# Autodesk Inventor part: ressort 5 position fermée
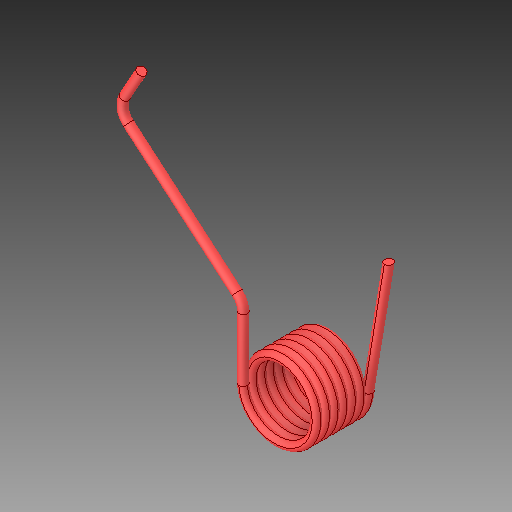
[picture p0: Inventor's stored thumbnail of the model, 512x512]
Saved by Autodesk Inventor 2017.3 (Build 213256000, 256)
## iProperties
Created: 2008-01
Part Number: ressort 5 position fermée
Material: Générique
Document SubType Name: Modeling
Designer: ficho
Density: 1 g/cm^3
Appearance: Par défaut
Author: ficho
Sending System: SolidWorks 2009
Last Author: christophe
Last Saved: 2011-02-11
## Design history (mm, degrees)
feature "Balayage3"
node "Solide1"
